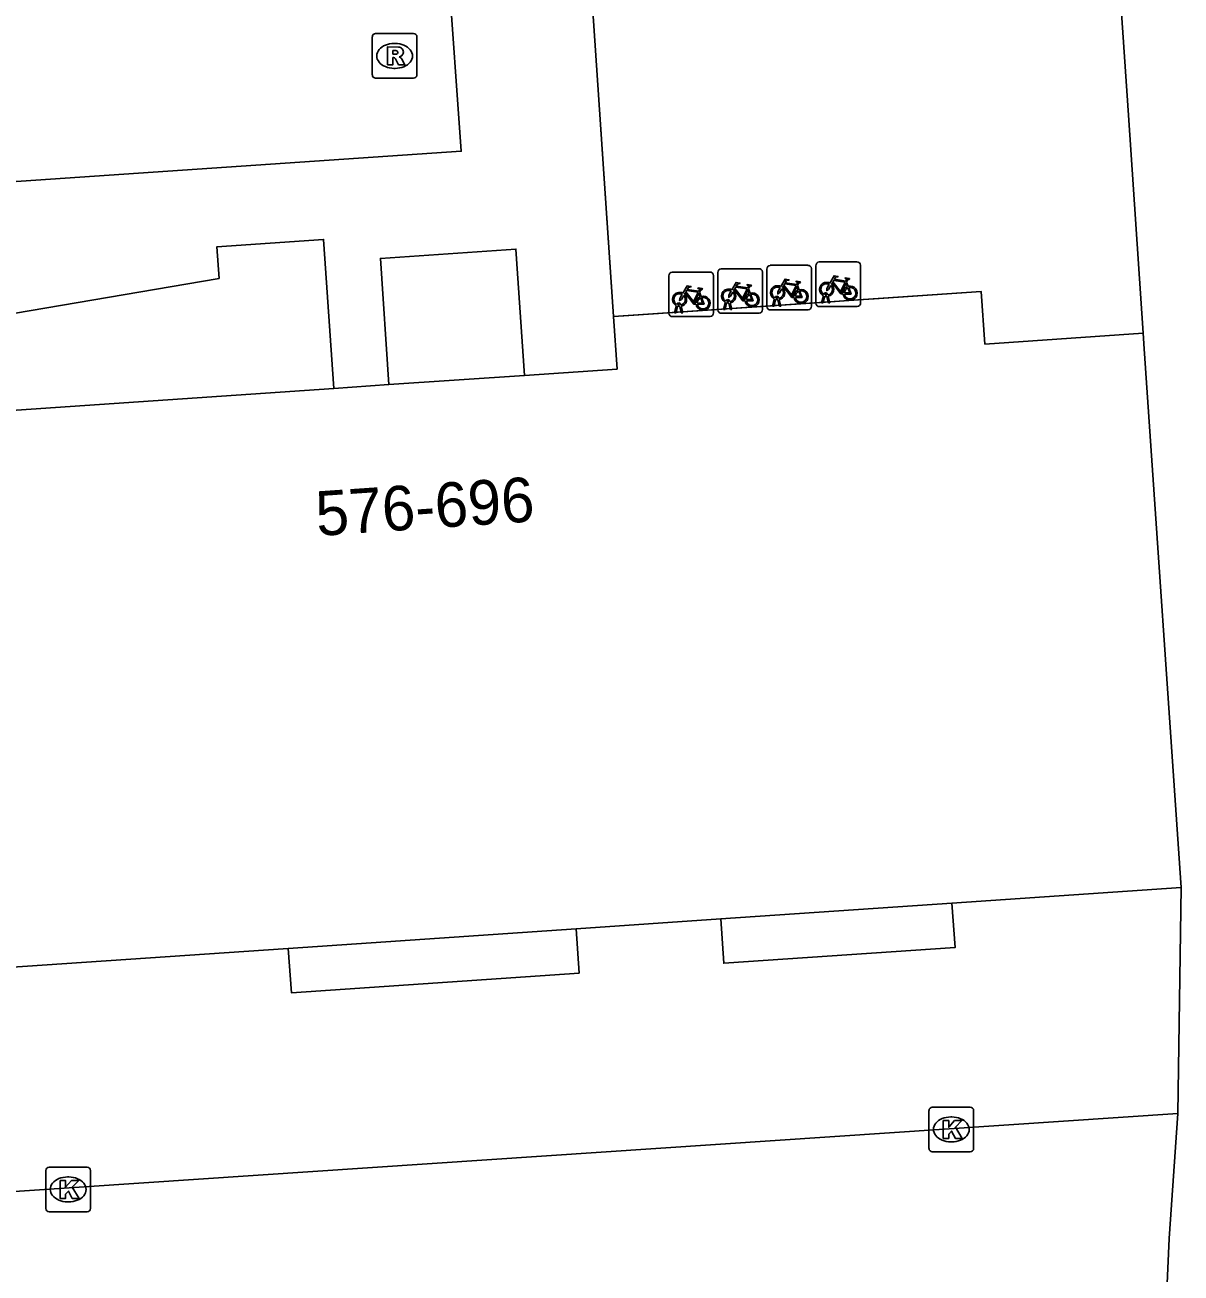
# Model space of a CAD drawing. Extents: x 161253 to 161848, y 384872 to 385383.
# Drawn here: x 161780.98 to 161806.91, y 385198.45 to 385226.45 of the extents above; entities that cross this region are included whole.
import ezdxf

# ---------------------------------------------------------------- set-up
doc = ezdxf.new("R2010")
doc.units = 0
for name, color, linetype in [('IMGEO_Fietsenrek', 7, 'Continuous'), ('IMGEO_Kolk', 7, 'Continuous'), ('IMGEO_Pand', 7, 'Continuous'), ('IMGEO_Pand_nummerreeks', 7, 'Continuous'), ('IMGEO_Pand_overbouw', 7, 'Continuous'), ('IMGEO_Parkeervlak_open', 7, 'Continuous'), ('IMGEO_Rijbaan_lokaal_open', 7, 'Continuous'), ('IMGEO_Rioolput', 7, 'Continuous'), ('IMGEO_Voetpad_open', 7, 'Continuous')]:
    doc.layers.add(name, color=color, linetype=linetype)

msp = doc.modelspace()

# ---------------------------------------------------------------- linework, layer by layer
at = {"layer": 'IMGEO_Fietsenrek'}
for p, q in [((161796.598, 385220.979), (161797.439, 385220.979)), ((161797.439, 385220.979), (161796.598, 385220.979)), ((161797.622, 385220.129), (161797.622, 385220.97)), ((161797.622, 385220.97), (161797.622, 385220.129)), ((161797.697, 385221.054), (161798.538, 385221.054)), ((161798.538, 385221.054), (161797.697, 385221.054)), ((161798.622, 385220.979), (161798.622, 385220.138)), ((161798.622, 385220.138), (161798.622, 385220.979)), ((161798.722, 385220.204), (161798.722, 385221.045)), ((161798.722, 385221.045), (161798.722, 385220.204)), ((161798.797, 385221.129), (161799.638, 385221.129)), ((161799.638, 385221.129), (161798.797, 385221.129)), ((161799.722, 385221.054), (161799.722, 385220.213)), ((161799.722, 385220.213), (161799.722, 385221.054)), ((161795.423, 385219.979), (161795.423, 385220.82)), ((161795.423, 385220.82), (161795.423, 385219.979)), ((161795.498, 385220.904), (161796.339, 385220.904)), ((161796.339, 385220.904), (161795.498, 385220.904)), ((161796.423, 385220.829), (161796.423, 385219.988)), ((161796.423, 385219.988), (161796.423, 385220.829)), ((161796.523, 385220.054), (161796.523, 385220.895)), ((161796.523, 385220.895), (161796.523, 385220.054)), ((161797.523, 385220.904), (161797.523, 385220.063)), ((161797.523, 385220.063), (161797.523, 385220.904)), ((161799.409, 385220.678), (161799.445, 385220.583)), ((161796.11, 385220.453), (161796.146, 385220.358)), ((161797.21, 385220.528), (161797.246, 385220.433)), ((161798.309, 385220.603), (161798.345, 385220.508)), ((161798.96, 385220.385), (161798.959, 385220.389)), ((161798.991, 385220.396), (161798.992, 385220.389)), ((161795.55, 385219.988), (161795.589, 385220.148)), ((161795.619, 385220.136), (161795.584, 385219.988)), ((161795.661, 385220.16), (161795.66, 385220.164)), ((161795.702, 385219.988), (161795.668, 385220.13)), ((161795.692, 385220.171), (161795.693, 385220.164)), ((161795.7, 385220.134), (161795.735, 385219.988)), ((161796.65, 385220.063), (161796.689, 385220.223)), ((161796.719, 385220.211), (161796.684, 385220.063)), ((161796.761, 385220.235), (161796.76, 385220.239)), ((161796.802, 385220.063), (161796.768, 385220.205)), ((161796.792, 385220.246), (161796.793, 385220.239)), ((161796.8, 385220.209), (161796.835, 385220.063)), ((161797.749, 385220.138), (161797.788, 385220.298)), ((161797.783, 385220.138), (161797.749, 385220.138)), ((161797.818, 385220.286), (161797.783, 385220.138)), ((161797.86, 385220.31), (161797.859, 385220.314)), ((161797.901, 385220.138), (161797.867, 385220.28)), ((161797.891, 385220.321), (161797.892, 385220.314)), ((161797.899, 385220.284), (161797.934, 385220.138)), ((161797.934, 385220.138), (161797.901, 385220.138)), ((161799.647, 385220.129), (161798.806, 385220.129)), ((161798.806, 385220.129), (161799.647, 385220.129)), ((161798.849, 385220.213), (161798.888, 385220.373)), ((161798.883, 385220.213), (161798.849, 385220.213)), ((161798.918, 385220.361), (161798.883, 385220.213)), ((161799.001, 385220.213), (161798.967, 385220.355)), ((161798.999, 385220.359), (161799.034, 385220.213)), ((161799.034, 385220.213), (161799.001, 385220.213)), ((161796.348, 385219.904), (161795.507, 385219.904)), ((161795.507, 385219.904), (161796.348, 385219.904)), ((161795.584, 385219.988), (161795.55, 385219.988)), ((161795.735, 385219.988), (161795.702, 385219.988)), ((161797.448, 385219.979), (161796.607, 385219.979)), ((161796.607, 385219.979), (161797.448, 385219.979)), ((161796.684, 385220.063), (161796.65, 385220.063)), ((161796.835, 385220.063), (161796.802, 385220.063)), ((161798.547, 385220.054), (161797.706, 385220.054)), ((161797.706, 385220.054), (161798.547, 385220.054))]:
    msp.add_line(p, q, dxfattribs=at)
for points in [[(161796.836, 385220.505), (161796.931, 385220.669), (161797.017, 385220.655), (161797.019, 385220.646), (161796.963, 385220.635), (161796.936, 385220.59), (161797.192, 385220.549)], [(161797.935, 385220.58), (161798.03, 385220.744), (161798.116, 385220.73), (161798.118, 385220.721), (161798.062, 385220.71), (161798.035, 385220.665), (161798.291, 385220.624)], [(161798.291, 385220.624), (161798.316, 385220.673), (161798.31, 385220.677), (161798.287, 385220.681), (161798.275, 385220.688), (161798.274, 385220.691), (161798.276, 385220.696), (161798.371, 385220.681), (161798.373, 385220.671), (161798.363, 385220.658), (161798.351, 385220.652), (161798.337, 385220.658), (161798.309, 385220.603)], [(161799.035, 385220.655), (161799.13, 385220.819), (161799.216, 385220.805), (161799.218, 385220.796), (161799.162, 385220.785), (161799.135, 385220.74), (161799.391, 385220.699)], [(161799.331, 385220.411), (161799.281, 385220.411), (161799.09, 385220.662), (161799.071, 385220.63)], [(161799.378, 385220.674), (161799.121, 385220.715), (161799.104, 385220.686), (161799.271, 385220.466), (161799.378, 385220.674)], [(161799.391, 385220.699), (161799.416, 385220.748), (161799.41, 385220.752), (161799.387, 385220.756), (161799.375, 385220.763), (161799.374, 385220.766), (161799.376, 385220.771), (161799.471, 385220.756), (161799.473, 385220.746), (161799.463, 385220.733), (161799.451, 385220.727), (161799.437, 385220.733), (161799.409, 385220.678)], [(161795.757, 385220.378), (161795.705, 385220.288), (161795.665, 385220.263), (161795.666, 385220.31), (161795.721, 385220.404)], [(161795.736, 385220.43), (161795.831, 385220.594), (161795.917, 385220.58), (161795.919, 385220.571), (161795.863, 385220.56), (161795.836, 385220.515), (161796.092, 385220.474)], [(161796.032, 385220.186), (161795.982, 385220.186), (161795.791, 385220.437), (161795.772, 385220.405)], [(161796.079, 385220.449), (161795.822, 385220.49), (161795.805, 385220.461), (161795.972, 385220.241), (161796.079, 385220.449)], [(161796.127, 385220.351), (161796.097, 385220.428), (161795.988, 385220.21), (161796.031, 385220.21)], [(161796.092, 385220.474), (161796.117, 385220.523), (161796.111, 385220.527), (161796.088, 385220.531), (161796.076, 385220.538), (161796.075, 385220.541), (161796.077, 385220.546), (161796.172, 385220.531), (161796.174, 385220.521), (161796.164, 385220.508), (161796.152, 385220.502), (161796.138, 385220.508), (161796.11, 385220.453)], [(161796.857, 385220.453), (161796.805, 385220.363), (161796.765, 385220.338), (161796.766, 385220.385), (161796.821, 385220.479)], [(161797.132, 385220.261), (161797.082, 385220.261), (161796.891, 385220.512), (161796.872, 385220.48)], [(161797.179, 385220.524), (161796.922, 385220.565), (161796.905, 385220.536), (161797.072, 385220.316), (161797.179, 385220.524)], [(161797.227, 385220.426), (161797.197, 385220.503), (161797.088, 385220.285), (161797.131, 385220.285)], [(161797.161, 385220.285), (161797.281, 385220.284), (161797.237, 385220.398)], [(161797.257, 385220.405), (161797.312, 385220.26), (161797.162, 385220.26)], [(161797.192, 385220.549), (161797.217, 385220.598), (161797.211, 385220.602), (161797.188, 385220.606), (161797.176, 385220.613), (161797.175, 385220.616), (161797.177, 385220.621), (161797.272, 385220.606), (161797.274, 385220.596), (161797.264, 385220.583), (161797.252, 385220.577), (161797.238, 385220.583), (161797.21, 385220.528)], [(161797.956, 385220.528), (161797.904, 385220.438), (161797.864, 385220.413), (161797.865, 385220.46), (161797.92, 385220.554)], [(161798.231, 385220.336), (161798.181, 385220.336), (161797.99, 385220.587), (161797.971, 385220.555)], [(161798.278, 385220.599), (161798.021, 385220.64), (161798.004, 385220.611), (161798.171, 385220.391), (161798.278, 385220.599)], [(161798.326, 385220.501), (161798.296, 385220.578), (161798.187, 385220.36), (161798.23, 385220.36)], [(161798.26, 385220.36), (161798.38, 385220.359), (161798.336, 385220.473)], [(161798.356, 385220.48), (161798.411, 385220.335), (161798.261, 385220.335)], [(161799.056, 385220.603), (161799.004, 385220.513), (161798.964, 385220.488), (161798.965, 385220.535), (161799.02, 385220.629)], [(161799.426, 385220.576), (161799.396, 385220.653), (161799.287, 385220.435), (161799.33, 385220.435)], [(161799.36, 385220.435), (161799.48, 385220.434), (161799.436, 385220.548)], [(161799.456, 385220.555), (161799.511, 385220.41), (161799.361, 385220.41)], [(161796.061, 385220.21), (161796.181, 385220.209), (161796.137, 385220.323)], [(161796.157, 385220.33), (161796.212, 385220.185), (161796.062, 385220.185)]]:
    msp.add_lwpolyline(points, dxfattribs=at)
for centre, radius, start, end in [((161796.601, 385220.901), 0.0779, 92.4484, 184.2845), ((161796.601, 385220.901), 0.0779, 92.4484, 184.2845), ((161797.445, 385220.901), 0.0779, 2.4484, 94.2845), ((161797.445, 385220.901), 0.0779, 2.4484, 94.2845), ((161797.7, 385220.976), 0.0779, 92.4484, 184.2845), ((161797.7, 385220.976), 0.0779, 92.4484, 184.2845), ((161798.544, 385220.976), 0.0779, 2.4484, 94.2845), ((161798.544, 385220.976), 0.0779, 2.4484, 94.2845), ((161798.8, 385221.051), 0.0779, 92.4484, 184.2845), ((161798.8, 385221.051), 0.0779, 92.4484, 184.2845), ((161799.644, 385221.051), 0.0779, 2.4484, 94.2845), ((161799.644, 385221.051), 0.0779, 2.4484, 94.2845), ((161795.501, 385220.826), 0.0779, 92.4484, 184.2845), ((161795.501, 385220.826), 0.0779, 92.4484, 184.2845), ((161796.345, 385220.826), 0.0779, 2.4484, 94.2845), ((161796.345, 385220.826), 0.0779, 2.4484, 94.2845), ((161798.962, 385220.514), 0.159, 62.6766, 242.1369), ((161795.663, 385220.289), 0.159, 62.6766, 242.1369), ((161795.663, 385220.289), 0.129, 63.3192, 238.903), ((161795.663, 385220.289), 0.129, 283.6043, 43.4302), ((161795.663, 385220.289), 0.159, 283.5766, 46.6042), ((161796.763, 385220.364), 0.159, 62.6766, 242.1369), ((161796.763, 385220.364), 0.129, 63.3192, 238.903), ((161796.763, 385220.364), 0.129, 283.6043, 43.4302), ((161796.763, 385220.364), 0.159, 283.5766, 46.6042), ((161797.29, 385220.28), 0.159, 113.3408, 178.3217), ((161797.29, 385220.28), 0.159, 187.0065, 105.7708), ((161797.29, 385220.28), 0.129, 113.923, 177.9556), ((161797.29, 385220.28), 0.129, 188.6715, 104.5883), ((161797.862, 385220.439), 0.159, 62.6766, 242.1369), ((161797.862, 385220.439), 0.129, 63.3192, 238.903), ((161797.862, 385220.439), 0.129, 283.6043, 43.4302), ((161797.862, 385220.439), 0.159, 283.5766, 46.6042), ((161798.389, 385220.355), 0.159, 113.3408, 178.3217), ((161798.389, 385220.355), 0.159, 187.0065, 105.7708), ((161798.389, 385220.355), 0.129, 113.923, 177.9556), ((161798.389, 385220.355), 0.129, 188.6715, 104.5883), ((161798.962, 385220.514), 0.129, 63.3192, 238.903), ((161798.942, 385220.385), 0.0499, 12.8025, 158.6934), ((161798.942, 385220.385), 0.0174, 12.8025, 163.4502), ((161798.962, 385220.514), 0.129, 253.415, 269.0204), ((161798.962, 385220.514), 0.129, 283.6043, 43.4302), ((161798.962, 385220.514), 0.159, 283.5766, 46.6042), ((161799.489, 385220.43), 0.159, 113.3408, 178.3217), ((161799.489, 385220.43), 0.159, 187.0065, 105.7708), ((161799.489, 385220.43), 0.129, 113.923, 177.9556), ((161799.489, 385220.43), 0.129, 188.6715, 104.5883), ((161795.643, 385220.16), 0.0499, 12.8025, 158.6934), ((161795.663, 385220.289), 0.159, 253.9967, 271.7867), ((161795.643, 385220.16), 0.0174, 12.8025, 163.4502), ((161795.663, 385220.289), 0.129, 253.415, 269.0204), ((161796.19, 385220.205), 0.159, 113.3408, 178.3217), ((161796.19, 385220.205), 0.159, 187.0065, 105.7708), ((161796.19, 385220.205), 0.129, 113.923, 177.9556), ((161796.19, 385220.205), 0.129, 188.6715, 104.5883), ((161796.743, 385220.235), 0.0499, 12.8025, 158.6934), ((161796.763, 385220.364), 0.159, 253.9967, 271.7867), ((161796.743, 385220.235), 0.0174, 12.8025, 163.4502), ((161796.763, 385220.364), 0.129, 253.415, 269.0204), ((161797.7, 385220.132), 0.0779, 182.4484, 274.2845), ((161797.7, 385220.132), 0.0779, 182.4484, 274.2845), ((161797.842, 385220.31), 0.0499, 12.8025, 158.6934), ((161797.862, 385220.439), 0.159, 253.9967, 271.7867), ((161797.842, 385220.31), 0.0174, 12.8025, 163.4502), ((161797.862, 385220.439), 0.129, 253.415, 269.0204), ((161798.544, 385220.132), 0.0779, 272.4484, 4.2845), ((161798.544, 385220.132), 0.0779, 272.4484, 4.2845), ((161798.8, 385220.207), 0.0779, 182.4484, 274.2845), ((161798.8, 385220.207), 0.0779, 182.4484, 274.2845), ((161798.962, 385220.514), 0.159, 253.9967, 271.7867), ((161799.644, 385220.207), 0.0779, 272.4484, 4.2845), ((161799.644, 385220.207), 0.0779, 272.4484, 4.2845), ((161795.501, 385219.982), 0.0779, 182.4484, 274.2845), ((161795.501, 385219.982), 0.0779, 182.4484, 274.2845), ((161796.345, 385219.982), 0.0779, 272.4484, 4.2845), ((161796.345, 385219.982), 0.0779, 272.4484, 4.2845), ((161796.601, 385220.057), 0.0779, 182.4484, 274.2845), ((161796.601, 385220.057), 0.0779, 182.4484, 274.2845), ((161797.445, 385220.057), 0.0779, 272.4484, 4.2845), ((161797.445, 385220.057), 0.0779, 272.4484, 4.2845)]:
    msp.add_arc(centre, radius, start, end, dxfattribs=at)
at = {"layer": 'IMGEO_Kolk'}
for p, q in [((161801.257, 385201.247), (161801.257, 385202.099)), ((161801.332, 385202.173), (161802.184, 385202.173)), ((161801.745, 385201.953), (161801.77, 385201.953)), ((161802.258, 385202.099), (161802.258, 385201.247)), ((161801.768, 385201.393), (161801.743, 385201.393)), ((161802.184, 385201.173), (161801.332, 385201.173)), ((161781.525, 385200.827), (161782.377, 385200.827)), ((161781.45, 385199.901), (161781.45, 385200.753)), ((161781.938, 385200.607), (161781.963, 385200.607)), ((161782.451, 385200.753), (161782.451, 385199.901)), ((161781.961, 385200.047), (161781.936, 385200.047)), ((161782.377, 385199.827), (161781.525, 385199.827))]:
    msp.add_line(p, q, dxfattribs=at)
for points in [[(161801.257, 385201.247), (161801.257, 385202.099)], [(161801.332, 385202.173), (161802.184, 385202.173)], [(161802.258, 385202.099), (161802.258, 385201.247)], [(161801.578, 385201.873), (161801.701, 385201.873), (161801.701, 385201.722), (161801.831, 385201.873), (161801.995, 385201.873), (161801.849, 385201.722), (161802.002, 385201.473), (161801.85, 385201.473), (161801.765, 385201.637), (161801.701, 385201.57), (161801.701, 385201.473), (161801.578, 385201.473), (161801.578, 385201.873)], [(161802.184, 385201.173), (161801.332, 385201.173)], [(161781.525, 385200.827), (161782.377, 385200.827)], [(161781.45, 385199.901), (161781.45, 385200.753)], [(161781.771, 385200.527), (161781.894, 385200.527), (161781.894, 385200.376), (161782.024, 385200.527), (161782.188, 385200.527), (161782.042, 385200.376), (161782.195, 385200.127), (161782.043, 385200.127), (161781.958, 385200.291), (161781.894, 385200.224), (161781.894, 385200.127), (161781.771, 385200.127), (161781.771, 385200.527)], [(161782.451, 385200.753), (161782.451, 385199.901)], [(161782.377, 385199.827), (161781.525, 385199.827)]]:
    msp.add_lwpolyline(points, dxfattribs=at)
for centre, start, end in [((161801.334, 385202.097), 91.552, 178.448), ((161801.334, 385202.097), 91.552, 178.448), ((161802.182, 385202.097), 1.552, 88.448), ((161802.182, 385202.097), 1.552, 88.448), ((161801.334, 385201.249), 181.552, 268.448), ((161801.334, 385201.249), 181.552, 268.448), ((161802.182, 385201.249), 271.552, 358.448), ((161802.182, 385201.249), 271.552, 358.448), ((161781.527, 385200.751), 91.552, 178.448), ((161781.527, 385200.751), 91.552, 178.448), ((161782.375, 385200.751), 1.552, 88.448), ((161782.375, 385200.751), 1.552, 88.448), ((161781.527, 385199.903), 181.552, 268.448), ((161781.527, 385199.903), 181.552, 268.448), ((161782.375, 385199.903), 271.552, 358.448), ((161782.375, 385199.903), 271.552, 358.448)]:
    msp.add_arc(centre, 0.0765, start, end, dxfattribs=at)
for centre, major_axis, ratio, start_param, end_param in [((161801.744, 385201.673), (-0.387, 0.002), 0.722429, 4.712389, 7.853982), ((161801.769, 385201.673), (-0.39, 0.002), 0.717154, 1.570796, 4.712389), ((161781.937, 385200.327), (-0.387, 0.002), 0.722429, 4.712389, 7.853982), ((161781.962, 385200.327), (-0.39, 0.002), 0.717154, 1.570796, 4.712389)]:
    msp.add_ellipse(centre, major_axis=major_axis, ratio=ratio, start_param=start_param, end_param=end_param, dxfattribs=at)
at = {"layer": 'IMGEO_Pand'}
for points in [[(161806.062, 385219.53), (161802.511, 385219.288), (161802.431, 385220.466), (161794.183, 385219.903)], [(161792.187, 385218.585), (161794.263, 385218.726), (161794.183, 385219.903)], [(161806.062, 385219.53), (161806.086, 385219.181), (161806.91, 385207.1)], [(161792.187, 385218.585), (161789.145, 385218.378)], [(161772.683, 385217.252), (161787.907, 385218.294)], [(161787.907, 385218.294), (161789.145, 385218.378)], [(161806.91, 385207.1), (161801.772, 385206.749)], [(161796.585, 385206.396), (161801.772, 385206.749)], [(161796.585, 385206.396), (161793.342, 385206.174)], [(161786.887, 385205.734), (161793.342, 385206.174)], [(161786.887, 385205.734), (161778.716, 385205.176)]]:
    msp.add_lwpolyline(points, dxfattribs=at)
at = {"layer": 'IMGEO_Pand_overbouw'}
msp.add_lwpolyline([(161794.183, 385219.903), (161794.528, 385219.927), (161799.049, 385220.235), (161799.658, 385220.277), (161800.025, 385220.302), (161802.431, 385220.466), (161802.511, 385219.288), (161806.062, 385219.53), (161805.728, 385224.419), (161805.407, 385229.116), (161805.036, 385234.554), (161804.45, 385243.135), (161804.116, 385248.022), (161802.347, 385247.903), (161803.617, 385228.996), (161794.586, 385228.39), (161794.006, 385237.024), (161795.016, 385237.092), (161794.874, 385239.212), (161793.848, 385239.143), (161793.301, 385247.294), (161792.323, 385247.228), (161793.611, 385228.31), (161794.123, 385220.789)], close=True, dxfattribs=at)
at = {"layer": 'IMGEO_Parkeervlak_open'}
for points in [[(161801.772, 385206.749), (161801.841, 385205.753), (161796.654, 385205.399), (161796.585, 385206.396)], [(161793.342, 385206.174), (161793.411, 385205.178), (161786.956, 385204.737), (161786.887, 385205.734)]]:
    msp.add_lwpolyline(points, dxfattribs=at)
at = {"layer": 'IMGEO_Rijbaan_lokaal_open'}
for points in [[(161806.835, 385202.034), (161771.932, 385199.693)], [(161806.835, 385202.034), (161806.647, 385199.228), (161806.537, 385196.879)]]:
    msp.add_lwpolyline(points, dxfattribs=at)
at = {"layer": 'IMGEO_Rioolput'}
for p, q in [((161788.772, 385225.325), (161788.772, 385226.177)), ((161788.847, 385226.251), (161789.699, 385226.251)), ((161789.26, 385226.031), (161789.285, 385226.031)), ((161789.773, 385226.177), (161789.773, 385225.325)), ((161789.283, 385225.471), (161789.258, 385225.471)), ((161789.699, 385225.251), (161788.847, 385225.251))]:
    msp.add_line(p, q, dxfattribs=at)
for points in [[(161788.772, 385225.325), (161788.772, 385226.177)], [(161788.847, 385226.251), (161789.699, 385226.251)], [(161789.773, 385226.177), (161789.773, 385225.325)], [(161789.361, 385225.949), (161789.109, 385225.951), (161789.109, 385225.551)], [(161789.109, 385225.551), (161789.233, 385225.551), (161789.233, 385225.713), (161789.244, 385225.713)], [(161789.287, 385225.87), (161789.233, 385225.87), (161789.233, 385225.789)], [(161789.233, 385225.789), (161789.285, 385225.789)], [(161789.291, 385225.684), (161789.362, 385225.551), (161789.502, 385225.551), (161789.437, 385225.677)], [(161789.699, 385225.251), (161788.847, 385225.251)]]:
    msp.add_lwpolyline(points, dxfattribs=at)
for centre, radius, start, end in [((161788.849, 385226.175), 0.0765, 91.552, 178.448), ((161788.849, 385226.175), 0.0765, 91.552, 178.448), ((161789.697, 385226.175), 0.0765, 1.552, 88.448), ((161789.697, 385226.175), 0.0765, 1.552, 88.448), ((161789.243, 385225.66), 0.0533, 26.0293, 88.6989), ((161789.269, 385225.978), 0.19, 274.7715, 282.9687), ((161789.293, 385225.774), 0.0964, 77.0061, 93.1865), ((161789.307, 385225.831), 0.0378, 276.6634, 79.6772), ((161789.36, 385225.839), 0.109, 350.3612, 89.416), ((161789.358, 385225.839), 0.112, 277.5842, 350.9817), ((161789.342, 385225.624), 0.108, 29.5134, 73.7905), ((161788.849, 385225.327), 0.0765, 181.552, 268.448), ((161788.849, 385225.327), 0.0765, 181.552, 268.448), ((161789.697, 385225.327), 0.0765, 271.552, 358.448), ((161789.697, 385225.327), 0.0765, 271.552, 358.448)]:
    msp.add_arc(centre, radius, start, end, dxfattribs=at)
for centre, major_axis, ratio, start_param, end_param in [((161789.259, 385225.751), (-0.387, 0.002), 0.722429, 4.712389, 7.853982), ((161789.284, 385225.751), (-0.39, 0.002), 0.717154, 1.570796, 4.712389)]:
    msp.add_ellipse(centre, major_axis=major_axis, ratio=ratio, start_param=start_param, end_param=end_param, dxfattribs=at)
at = {"layer": 'IMGEO_Voetpad_open'}
for points in [[(161802.83, 385266.843), (161804.116, 385248.022), (161804.45, 385243.135), (161805.036, 385234.554), (161805.407, 385229.116), (161805.728, 385224.419), (161806.062, 385219.53)], [(161794.183, 385219.903), (161793.611, 385228.31), (161792.323, 385247.228), (161791.041, 385266.055)], [(161790.47, 385227.718), (161790.768, 385223.612), (161769.376, 385222.155), (161769.034, 385226.639)], [(161772.683, 385217.252), (161772.592, 385218.59), (161785.334, 385220.762), (161785.285, 385221.471), (161787.679, 385221.635), (161787.907, 385218.294)], [(161789.145, 385218.378), (161788.952, 385221.21), (161791.994, 385221.418), (161792.187, 385218.585)], [(161806.91, 385207.1), (161806.835, 385202.034)]]:
    msp.add_lwpolyline(points, dxfattribs=at)

# ---------------------------------------------------------------- texts
at = {"layer": 'IMGEO_Pand_nummerreeks'}
msp.add_text('576-696', height=1, rotation=3.8904, dxfattribs=at).set_placement((161787.536, 385214.982))

doc.saveas('drawing.dxf')
